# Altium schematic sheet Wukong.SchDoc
size A4; PageSetup: Record=PageOptions¦CenterHorizontal=True¦CenterVertical=True¦PrintScale=1.00¦XCorrection=1.00¦YCorrection=1.00¦PrintKind=0¦BorderSize=5000000¦LeftOffset=0¦BottomOffset=0¦Orientation=2¦PaperLength=1000¦PaperWidth=1000¦Scale=100¦PaperSource=7¦PrintQuality=-3¦MediaType=1¦DitherType=10¦PrintScaleMode=1¦PaperKind=A4¦PaperIndex=9
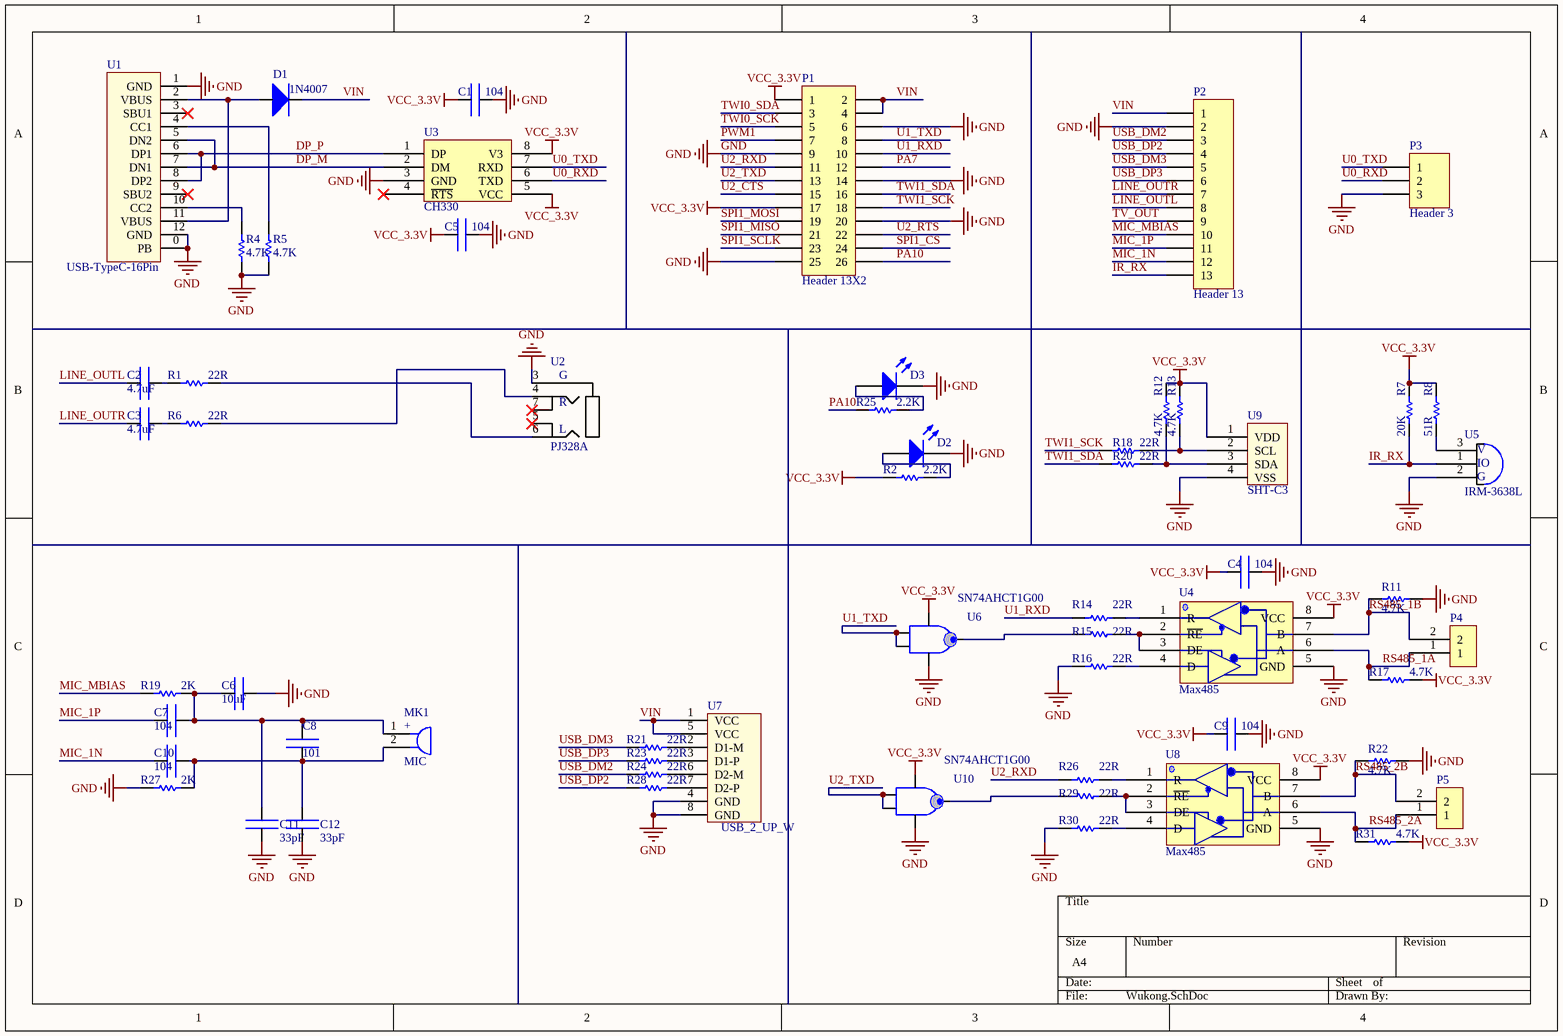
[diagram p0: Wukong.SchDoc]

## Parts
C1  value 104  [C0603]  (hidden comment: CAP)
C2  value 4.7uF  [C0603]  (hidden comment: CAP)
C3  value 4.7uF  [C0603]  (hidden comment: CAP)
C4  value 104  [C0603]  (hidden comment: CAP)
C5  value 104  [C0603]  (hidden comment: CAP)
C6  value 10uF  [C0805]  (hidden comment: CAP)
C7  value 104  [C0603]  (hidden comment: CAP)
C8  value 101  [C0603]  (hidden comment: CAP)
C9  value 104  [C0603]  (hidden comment: CAP)
C10  value 104  [C0603]  (hidden comment: CAP)
C11  value 33pF  [C0603]  (hidden comment: CAP)
C12  value 33pF  [C0603]  (hidden comment: CAP)
D1  1N4007  [DO-214AC]
D2  LED  [LED_0805]  (value not drawn)
D3  LED  [LED_0805]  (value not drawn)
MK1  MIC  [MIC]
P1  Header 13X2  [HDR2X13]
P2  Header 13  [HDR1X13]
P3  Header 3  [HDR1X3]
P4  WJ15EDGRC-3.81-2P6GR  [WJ15EDGRC-3.81-2P6GR]  (value not drawn)
P5  WJ15EDGRC-3.81-2P6GR  [WJ15EDGRC-3.81-2P6GR]  (value not drawn)
R1  Res: 22R  [R0603]  (hidden comment: RES)
R2  Res: 2.2K  [R0603]  (hidden comment: RES)
R4  Res: 4.7K  [R0603]  (hidden comment: RES)
R5  Res: 4.7K  [R0603]  (hidden comment: RES)
R6  Res: 22R  [R0603]  (hidden comment: RES)
R7  Res: 20K  [R0603]  (hidden comment: RES)
R8  Res: 51R  [R0603]  (hidden comment: RES)
R11  Res: 4.7K  [R0603]  (hidden comment: RES)
R12  value 4.7K  [R0603]  (hidden comment: RES)
R13  value 4.7K  [R0603]  (hidden comment: RES)
R14  Res: 22R  [R0603]  (hidden comment: RES)
R15  Res: 22R  [R0603]  (hidden comment: RES)
R16  Res: 22R  [R0603]  (hidden comment: RES)
R17  Res: 4.7K  [R0603]  (hidden comment: RES)
R18  Res: 22R  [R0603]  (hidden comment: RES)
R19  Res: 2K  [R0603]  (hidden comment: RES)
R20  Res: 22R  [R0603]  (hidden comment: RES)
R21  Res: 22R  [R0603]  (hidden comment: RES)
R22  Res: 4.7K  [R0603]  (hidden comment: RES)
R23  Res: 22R  [R0603]  (hidden comment: RES)
R24  Res: 22R  [R0603]  (hidden comment: RES)
R25  Res: 2.2K  [R0603]  (hidden comment: RES)
R26  Res: 22R  [R0603]  (hidden comment: RES)
R27  Res: 2K  [R0603]  (hidden comment: RES)
R28  Res: 22R  [R0603]  (hidden comment: RES)
R29  Res: 22R  [R0603]  (hidden comment: RES)
R30  Res: 22R  [R0603]  (hidden comment: RES)
R31  Res: 4.7K  [R0603]  (hidden comment: RES)
U1  USB-TypeC-16Pin  [USB-TYPE-C-16PIN]
U2  PJ328A  [PJ-328A]
U3  CH330  [SOIC-8]
U4  Max485  [SOIC-8]
U5  IRM-3638L  [IRM-3638L]
U6  SN74AHCT1G00  [SOT-235]
U7  USB_2_UP_W  [USB_2_UP_W]
U8  Max485  [SOIC-8]
U9  SHT-C3  [SHTC3]
U10  SN74AHCT1G00  [SOT-235]

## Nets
GND: C1.2 C4.2 C5.2 C6.2 C9.2 C11.1 C12.1 D2.2(K) D3.2(K) P1.6 P1.9 P1.14 P1.20 P1.25 P2.2 P3.3 R4.2 R5.2 R11.2 R16.2 R22.2 R27.1 R30.2 U1.0(PB) U1.1(GND) U1.12(GND) U2.3 U3.3(GND) U4.5(GND) U5.2(VSS) U6.3(GND) U7.4(GND) U7.8(GND) U8.5(GND) U9.4(VSS) U10.3(GND)
VCC_3.3V: C1.1 C4.1 C5.1 C9.1 P1.1 P1.17 R2.2 R7.1 R8.1 R12.2 R13.2 R17.1 R31.1 U3.5(VCC) U3.8(V3) U4.8(VCC) U6.5(VCC) U8.8(VCC) U9.1(VDD) U10.5(VCC)
DP_M: U1.5(DN2) U1.7(DN1) U3.2(DM)
DP_P: U1.6(DP1) U1.8(DP2) U3.1(DP)
IR_RX: P2.13 R7.2 U5.1(IO)
LINE_OUTL: C2.1 P2.8
LINE_OUTR: C3.1 P2.7
MIC_1N: C10.1 P2.12
MIC_1P: C7.1 P2.11
MIC_MBIAS: P2.10 R19.1
PA7: P1.12
PA10: P1.26 R25.2
PWM1: P1.7
RS485_1A: P4.1 R17.2 U4.6(A)
RS485_1B: P4.2 R11.1 U4.7(B)
RS485_2A: P5.1 R31.2 U8.6(A)
RS485_2B: P5.2 R22.1 U8.7(B)
SPI1_CS: P1.24
SPI1_MISO: P1.21
SPI1_MOSI: P1.19
SPI1_SCLK: P1.23
TV_OUT: P2.9
TWI0_SCK: P1.5
TWI0_SDA: P1.3
TWI1_SCK: P1.18 R18.2
TWI1_SDA: P1.16 R20.2
U0_RXD: P3.2 U3.6(TXD)
U0_TXD: P3.1 U3.7(RXD)
U1_RXD: P1.10 R14.2
U1_TXD: P1.8 U6.1(INA) U6.2(INB)
U2_CTS: P1.15
U2_RTS: P1.22
U2_RXD: P1.11 R26.2
U2_TXD: P1.13 U10.1(INA) U10.2(INB)
USB_DM2: P2.3 R24.2
USB_DM3: P2.5 R21.2
USB_DP2: P2.4 R28.2
USB_DP3: P2.6 R23.2
VIN: D1.2 P1.2 P1.4 P2.1 U7.1(VCC) U7.5(VCC)
NetC2_2: C2.2 R1.2
NetC3_2: C3.2 R6.2
NetC6_1: C6.1 C7.2 C8.2 C11.2 MK1.1 R19.2
NetC8_1: C8.1 C10.2 C12.2 MK1.2 R27.2
NetD1_1: D1.1 U1.2(VBUS) U1.11(VBUS)
NetD2_1: D2.1(A) R2.1
NetD3_1: D3.1(A) R25.1
NetR1_1: R1.1 U2.6
NetR4_1: R4.1 U1.10(CC2)
NetR5_1: R5.1 U1.4(CC1)
NetR6_1: R6.1 U2.4
NetR8_2: R8.2 U5.3(VDD)
NetR12_1: R12.1 R20.1 U9.3(SDA)
NetR13_1: R13.1 R18.1 U9.2(SCL)
NetR14_1: R14.1 U4.1(R)
NetR15_1: R15.1 U4.2(~{RE}) U4.3(DE)
NetR15_2: R15.2 U6.4(OUT)
NetR16_1: R16.1 U4.4(D)
NetR21_1: R21.1 U7.2(D1-M)
NetR23_1: R23.1 U7.3(D1-P)
NetR24_1: R24.1 U7.6(D2-M)
NetR26_1: R26.1 U8.1(R)
NetR28_1: R28.1 U7.7(D2-P)
NetR29_1: R29.1 U8.2(~{RE}) U8.3(DE)
NetR29_2: R29.2 U10.4(OUT)
NetR30_1: R30.1 U8.4(D)

Not connected (* = marked no-connect by the designer): U1 3(SBU1)* 9(SBU2)*; U2 5* 7*; U3 4(~{RTS})*

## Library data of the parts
C1-C12 = 无极电容
D1 = 二极管
MK1 = MIC: 咪头，驻极体话筒
P1 = Header 13X2: Header, 13-Pin, Dual row
P2 = Header 13: Header, 13-Pin
P3 = Header 3: Header, 3-Pin
P4 P5 = WJ15EDGRC-3.81-2P6GR: 3.81-2P-Green-90
R1 R2 R4-R8 R11-R31 = RES: 电阻
U2 = PJ-328A: 3.5mm音频接口
U3 = CH330: USB 转串口
U4 U8 = Max485: MAX-485
U5 = IRM-3638L: 红外接收头，38KHz,2.7-5.5V
U6 U10 = SN74AHCT1G00: 双输入与非门
U7 = USB*2: 双层USB接口，上接触式，90度弯
U9 = SHT-C3: 温湿度传感器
